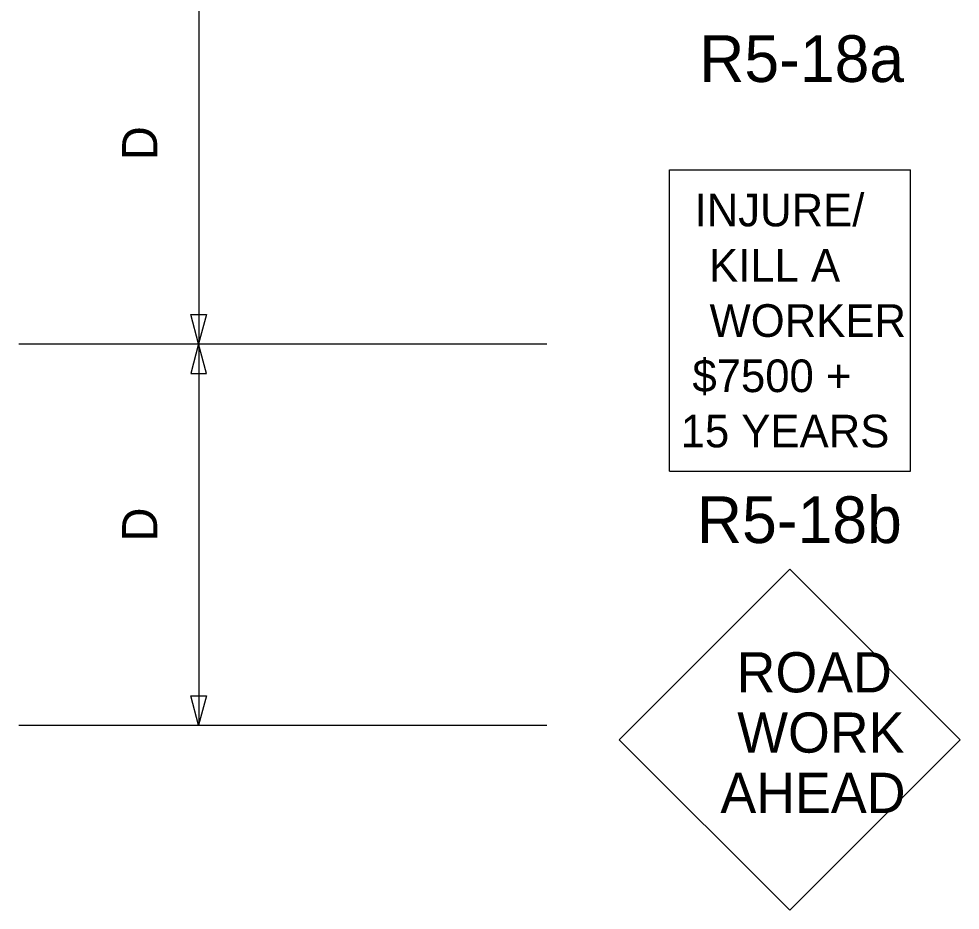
# Model space of a CAD drawing. Extents: x 19023 to 20747, y 5121 to 6119.
# Drawn here: x 19331.8 to 19519.2, y 5316.6 to 5494 of the extents above; entities that cross this region are included whole.
import ezdxf

# ---------------------------------------------------------------- set-up
doc = ezdxf.new("R2010")
doc.units = 0
doc.layers.add('TRAFFIC_SIGNS_PR', color=7, linetype='Continuous')
doc.layers.add('TYPICAL_TEXT_DIMEN_PR', color=7, linetype='Continuous')

msp = doc.modelspace()

# ---------------------------------------------------------------- linework, layer by layer
at = {"layer": 'TRAFFIC_SIGNS_PR'}
for p, q in [((19461.31, 5403.979), (19461.31, 5463.979)), ((19461.31, 5463.979), (19509.31, 5463.979)), ((19509.31, 5403.979), (19509.31, 5463.979)), ((19461.31, 5403.979), (19509.31, 5403.979)), ((19485.25, 5384.474), (19451.309, 5350.533)), ((19519.191, 5350.533), (19485.25, 5384.474)), ((19451.309, 5350.533), (19485.25, 5316.592)), ((19485.25, 5316.592), (19519.191, 5350.533))]:
    msp.add_line(p, q, dxfattribs=at)
at = {"layer": 'TYPICAL_TEXT_DIMEN_PR'}
for p, q in [((19367.574, 5581.162), (19367.574, 5353.414)), ((19367.558, 5429.339), (19365.987, 5435.201)), ((19365.987, 5435.201), (19367.558, 5435.201)), ((19367.558, 5435.201), (19369.129, 5435.201)), ((19369.129, 5435.201), (19367.558, 5429.339)), ((19331.757, 5429.331), (19436.891, 5429.331)), ((19367.558, 5429.323), (19365.987, 5423.461)), ((19369.129, 5423.461), (19367.558, 5429.323)), ((19365.987, 5423.461), (19367.558, 5423.461)), ((19367.558, 5423.461), (19369.129, 5423.461)), ((19367.558, 5353.422), (19365.987, 5359.284)), ((19365.987, 5359.284), (19367.558, 5359.284)), ((19367.558, 5359.284), (19369.129, 5359.284)), ((19369.129, 5359.284), (19367.558, 5353.422)), ((19331.757, 5353.414), (19436.891, 5353.414))]:
    msp.add_line(p, q, dxfattribs=at)

# ---------------------------------------------------------------- texts
at = {"layer": 'TRAFFIC_SIGNS_PR'}
for s, height, p in [('R5-18a', 9.3, (19467.237, 5481.474)), ('INJURE/', 6.5, (19466.312, 5452.73)), ('KILL A', 6.5, (19469.188, 5441.73)), ('WORKER', 6.5, (19469.283, 5430.73)), ('$7500 +', 6.5, (19465.874, 5419.731)), ('15 YEARS', 6.5, (19463.537, 5408.731)), ('R5-18b', 9.3, (19466.783, 5389.68)), ('ROAD', 8, (19474.677, 5359.952)), ('WORK', 8, (19474.813, 5347.952)), ('AHEAD', 8, (19471.451, 5335.952))]:
    msp.add_text(s, height=height, dxfattribs=at).set_placement(p)
at = {"layer": 'TYPICAL_TEXT_DIMEN_PR'}
for p in [(19359.321, 5465.91), (19359.321, 5389.993)]:
    msp.add_text('D', height=7, rotation=90, dxfattribs=at).set_placement(p)

doc.saveas('drawing.dxf')
